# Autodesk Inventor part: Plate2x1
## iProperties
Created: 2006-02
Part Number: Plate2x1
Material: Stainless Steel
Document SubType Name: Modeling
Designer: 40664
Mass: 189072 g
Surface Area: 47430 cm^2
Volume: 23400 cm^3
Density: 8.08 g/cm^3
CSToolsMass: 189.0
CSToolsVolume: 23400000.0
CSToolsArea: 47430.0
Author: 40664
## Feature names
1. Extrusion2
